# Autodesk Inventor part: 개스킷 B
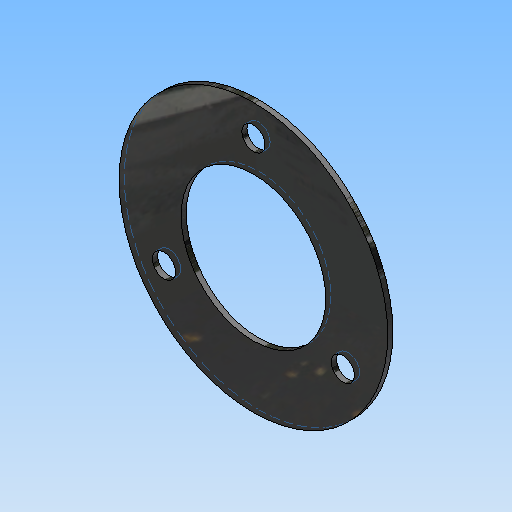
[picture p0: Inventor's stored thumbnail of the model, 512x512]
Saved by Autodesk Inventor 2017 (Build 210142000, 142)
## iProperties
Created: 2020-04
Part Number: 개스킷 B
Material: 고무
Document SubType Name: Modeling
Designer: mduedu
Density: 0.93 g/cm^3
Mass: 1.35803 g
Surface Area: 32.1424 cm^2
Volume: 1.46025 cm^3
Appearance: 고무 - 검은색 - 버전 1.1
Author: mduedu
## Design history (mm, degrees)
sketch "스케치1"
  geometry: C1 r 26 at (0, 0); 1 further point
  constraints: 1 centre point, 1 coincident
  dimensions: "d0" = 52 diameter of C1
extrude "돌출1" new body sketch "스케치1" distance "d1" = 1; taper "d2" = 0 deg
sketch "스케치3" dims "d6" = 40
  geometry: 3 further points
  constraints: 2 vertical alignment, 1 coincident, 2 other
hole "구멍1" sketch "스케치3" at (0, 20) diameter "d7" = 4.5; stored, may be unused: countersink angle "d11" = 90 deg, drill point angle "d13" = 118 deg; dims "d8" = 6, "d9" = 4, "d10" = 2, "d12" = 8
sketch "스케치4"
  geometry: C1 r 14 at (0, 0); 1 further point
  constraints: 1 centre point, 1 coincident
  dimensions: "d17" = 28 diameter of C1
extrude "돌출3" cut sketch "스케치4" stored distance "d18" = 1; taper "d19" = 0 deg
node "솔리드1"
pattern_circular "원형 패턴1" dims angle "d15" = 360 deg
